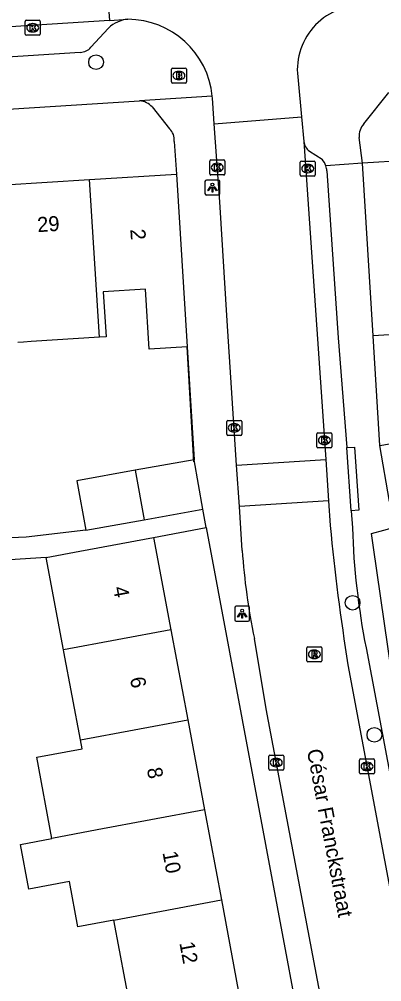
# Model space of a CAD drawing. Extents: x 159053 to 160041, y 380450 to 381422.
# Drawn here: x 159871.5 to 159895.7, y 380943.6 to 381007.6 of the extents above; entities that cross this region are included whole.
import ezdxf

# ---------------------------------------------------------------- set-up
doc = ezdxf.new("R2010")
doc.units = 0
for name, color, linetype in [('IMGEO_Boom', 7, 'Continuous'), ('IMGEO_Brandkraan', 7, 'Continuous'), ('IMGEO_Kolk', 7, 'Continuous'), ('IMGEO_Lichtpunt', 7, 'Continuous'), ('IMGEO_Muur', 7, 'Continuous'), ('IMGEO_Openbare_ruimte_label', 7, 'Continuous'), ('IMGEO_Pand', 7, 'Continuous'), ('IMGEO_Pand_nummerreeks', 7, 'Continuous'), ('IMGEO_Rijbaan_lokaal_open', 7, 'Continuous'), ('IMGEO_Rioolput', 7, 'Continuous'), ('IMGEO_Voetpad_open', 7, 'Continuous')]:
    doc.layers.add(name, color=color, linetype=linetype)

msp = doc.modelspace()

# ---------------------------------------------------------------- linework, layer by layer
at = {"layer": 'IMGEO_Boom'}
for centre in [(159876.626, 381004.767), (159893.724, 380968.791), (159895.174, 380960.006)]:
    msp.add_circle(centre, 0.489, dxfattribs=at)
at = {"layer": 'IMGEO_Brandkraan'}
for p, q in [((159881.646, 381003.451), (159881.646, 381004.303)), ((159881.721, 381004.377), (159882.573, 381004.377)), ((159882.134, 381004.157), (159882.159, 381004.157)), ((159882.647, 381004.303), (159882.647, 381003.451)), ((159882.573, 381003.377), (159881.721, 381003.377)), ((159882.157, 381003.597), (159882.132, 381003.597))]:
    msp.add_line(p, q, dxfattribs=at)
for points in [[(159881.646, 381003.451), (159881.646, 381004.303)], [(159881.721, 381004.377), (159882.573, 381004.377)], [(159881.994, 381004.077), (159881.994, 381003.677), (159882.207, 381003.677)], [(159882.225, 381004.077), (159881.994, 381004.077)], [(159882.173, 381003.996), (159882.119, 381003.996), (159882.119, 381003.92)], [(159882.647, 381004.303), (159882.647, 381003.451)], [(159882.573, 381003.377), (159881.721, 381003.377)], [(159882.119, 381003.92), (159882.172, 381003.92)], [(159882.181, 381003.844), (159882.119, 381003.844), (159882.119, 381003.763)], [(159882.119, 381003.763), (159882.181, 381003.763)]]:
    msp.add_lwpolyline(points, dxfattribs=at)
for centre, radius, start, end in [((159881.723, 381004.301), 0.0765, 91.55205, 178.44795), ((159881.723, 381004.301), 0.0765, 91.55205, 178.44795), ((159882.174, 381003.958), 0.0379, 267.82845, 90.93552), ((159882.229, 381003.932), 0.145, 59.4692, 91.53667), ((159882.254, 381003.979), 0.0922, 285.51372, 58.15012), ((159882.571, 381004.301), 0.0765, 1.55205, 88.44795), ((159882.571, 381004.301), 0.0765, 1.55205, 88.44795), ((159881.723, 381003.453), 0.0765, 181.55205, 268.44795), ((159881.723, 381003.453), 0.0765, 181.55205, 268.44795), ((159882.182, 381003.803), 0.0404, 269.87594, 90.50774), ((159882.213, 381003.928), 0.251, 268.66757, 293.53466), ((159882.259, 381003.787), 0.105, 301.31148, 78.98903), ((159882.571, 381003.453), 0.0765, 271.55205, 358.44795), ((159882.571, 381003.453), 0.0765, 271.55205, 358.44795)]:
    msp.add_arc(centre, radius, start, end, dxfattribs=at)
for centre, major_axis, ratio, start_param, end_param in [((159882.133, 381003.877), (-0.387, 0.002), 0.722429, 4.712389, 7.853982), ((159882.158, 381003.877), (-0.39, 0.002), 0.717154, 1.570796, 4.712389)]:
    msp.add_ellipse(centre, major_axis=major_axis, ratio=ratio, start_param=start_param, end_param=end_param, dxfattribs=at)
at = {"layer": 'IMGEO_Kolk'}
for p, q in [((159871.908, 381006.63), (159871.908, 381007.482)), ((159871.983, 381007.556), (159872.835, 381007.556)), ((159872.396, 381007.336), (159872.421, 381007.336)), ((159872.909, 381007.482), (159872.909, 381006.63)), ((159872.835, 381006.556), (159871.983, 381006.556)), ((159872.419, 381006.776), (159872.394, 381006.776)), ((159884.282, 380998.259), (159885.134, 380998.259)), ((159884.207, 380997.333), (159884.207, 380998.185)), ((159884.695, 380998.039), (159884.72, 380998.039)), ((159885.208, 380998.185), (159885.208, 380997.333)), ((159890.234, 380997.259), (159890.234, 380998.111)), ((159890.309, 380998.185), (159891.161, 380998.185)), ((159890.722, 380997.965), (159890.747, 380997.965)), ((159891.235, 380998.111), (159891.235, 380997.259)), ((159885.134, 380997.259), (159884.282, 380997.259)), ((159884.718, 380997.479), (159884.693, 380997.479)), ((159891.161, 380997.185), (159890.309, 380997.185)), ((159890.745, 380997.405), (159890.72, 380997.405)), ((159885.409, 380980.932), (159886.261, 380980.932)), ((159885.334, 380980.006), (159885.334, 380980.858)), ((159885.822, 380980.712), (159885.847, 380980.712)), ((159886.335, 380980.858), (159886.335, 380980.006)), ((159886.261, 380979.932), (159885.409, 380979.932)), ((159885.845, 380980.152), (159885.82, 380980.152)), ((159891.344, 380979.177), (159891.344, 380980.029)), ((159891.419, 380980.103), (159892.271, 380980.103)), ((159891.832, 380979.883), (159891.857, 380979.883)), ((159892.345, 380980.029), (159892.345, 380979.177)), ((159892.271, 380979.103), (159891.419, 380979.103)), ((159891.855, 380979.323), (159891.83, 380979.323)), ((159888.134, 380957.733), (159888.134, 380958.585)), ((159888.209, 380958.659), (159889.061, 380958.659)), ((159889.135, 380958.585), (159889.135, 380957.733)), ((159888.645, 380957.879), (159888.62, 380957.879)), ((159888.622, 380958.439), (159888.647, 380958.439)), ((159894.185, 380957.477), (159894.185, 380958.329)), ((159894.26, 380958.403), (159895.112, 380958.403)), ((159894.673, 380958.183), (159894.698, 380958.183)), ((159895.186, 380958.329), (159895.186, 380957.477)), ((159889.061, 380957.659), (159888.209, 380957.659)), ((159895.112, 380957.403), (159894.26, 380957.403)), ((159894.696, 380957.623), (159894.671, 380957.623))]:
    msp.add_line(p, q, dxfattribs=at)
for points in [[(159871.908, 381006.63), (159871.908, 381007.482)], [(159871.983, 381007.556), (159872.835, 381007.556)], [(159872.229, 381007.256), (159872.352, 381007.256), (159872.352, 381007.105), (159872.482, 381007.256), (159872.646, 381007.256), (159872.5, 381007.105), (159872.653, 381006.856), (159872.501, 381006.856), (159872.416, 381007.02), (159872.352, 381006.953), (159872.352, 381006.856), (159872.229, 381006.856), (159872.229, 381007.256)], [(159872.909, 381007.482), (159872.909, 381006.63)], [(159872.835, 381006.556), (159871.983, 381006.556)], [(159884.282, 380998.259), (159885.134, 380998.259)], [(159884.207, 380997.333), (159884.207, 380998.185)], [(159884.528, 380997.959), (159884.651, 380997.959), (159884.651, 380997.808), (159884.781, 380997.959), (159884.945, 380997.959), (159884.799, 380997.808), (159884.952, 380997.559), (159884.8, 380997.559), (159884.715, 380997.723), (159884.651, 380997.656), (159884.651, 380997.559), (159884.528, 380997.559), (159884.528, 380997.959)], [(159885.208, 380998.185), (159885.208, 380997.333)], [(159890.234, 380997.259), (159890.234, 380998.111)], [(159890.309, 380998.185), (159891.161, 380998.185)], [(159890.555, 380997.885), (159890.678, 380997.885), (159890.678, 380997.734), (159890.808, 380997.885), (159890.972, 380997.885), (159890.826, 380997.734), (159890.979, 380997.485), (159890.827, 380997.485), (159890.742, 380997.649), (159890.678, 380997.582), (159890.678, 380997.485), (159890.555, 380997.485), (159890.555, 380997.885)], [(159891.235, 380998.111), (159891.235, 380997.259)], [(159885.134, 380997.259), (159884.282, 380997.259)], [(159891.161, 380997.185), (159890.309, 380997.185)], [(159885.409, 380980.932), (159886.261, 380980.932)], [(159885.334, 380980.006), (159885.334, 380980.858)], [(159885.655, 380980.632), (159885.778, 380980.632), (159885.778, 380980.481), (159885.908, 380980.632), (159886.072, 380980.632), (159885.926, 380980.481), (159886.079, 380980.232), (159885.927, 380980.232), (159885.842, 380980.396), (159885.778, 380980.329), (159885.778, 380980.232), (159885.655, 380980.232), (159885.655, 380980.632)], [(159886.335, 380980.858), (159886.335, 380980.006)], [(159886.261, 380979.932), (159885.409, 380979.932)], [(159891.344, 380979.177), (159891.344, 380980.029)], [(159891.419, 380980.103), (159892.271, 380980.103)], [(159891.665, 380979.803), (159891.788, 380979.803), (159891.788, 380979.652), (159891.918, 380979.803), (159892.082, 380979.803), (159891.936, 380979.652), (159892.089, 380979.403), (159891.937, 380979.403), (159891.852, 380979.567), (159891.788, 380979.5), (159891.788, 380979.403), (159891.665, 380979.403), (159891.665, 380979.803)], [(159892.345, 380980.029), (159892.345, 380979.177)], [(159892.271, 380979.103), (159891.419, 380979.103)], [(159888.134, 380957.733), (159888.134, 380958.585)], [(159888.209, 380958.659), (159889.061, 380958.659)], [(159889.135, 380958.585), (159889.135, 380957.733)], [(159888.455, 380958.359), (159888.578, 380958.359), (159888.578, 380958.208), (159888.708, 380958.359), (159888.872, 380958.359), (159888.726, 380958.208), (159888.879, 380957.959), (159888.727, 380957.959), (159888.642, 380958.123), (159888.578, 380958.056), (159888.578, 380957.959), (159888.455, 380957.959), (159888.455, 380958.359)], [(159894.185, 380957.477), (159894.185, 380958.329)], [(159894.26, 380958.403), (159895.112, 380958.403)], [(159894.506, 380958.103), (159894.629, 380958.103), (159894.629, 380957.952), (159894.759, 380958.103), (159894.923, 380958.103), (159894.777, 380957.952), (159894.93, 380957.703), (159894.778, 380957.703), (159894.693, 380957.867), (159894.629, 380957.8), (159894.629, 380957.703), (159894.506, 380957.703), (159894.506, 380958.103)], [(159895.186, 380958.329), (159895.186, 380957.477)], [(159889.061, 380957.659), (159888.209, 380957.659)], [(159895.112, 380957.403), (159894.26, 380957.403)]]:
    msp.add_lwpolyline(points, dxfattribs=at)
for centre, start, end in [((159871.985, 381007.48), 91.55205, 178.44795), ((159871.985, 381007.48), 91.55205, 178.44795), ((159872.833, 381007.48), 1.55205, 88.44795), ((159872.833, 381007.48), 1.55205, 88.44795), ((159871.985, 381006.632), 181.55205, 268.44795), ((159871.985, 381006.632), 181.55205, 268.44795), ((159872.833, 381006.632), 271.55205, 358.44795), ((159872.833, 381006.632), 271.55205, 358.44795), ((159884.284, 380998.183), 91.55205, 178.44795), ((159884.284, 380998.183), 91.55205, 178.44795), ((159885.132, 380998.183), 1.55205, 88.44795), ((159885.132, 380998.183), 1.55205, 88.44795), ((159890.311, 380998.109), 91.55205, 178.44795), ((159890.311, 380998.109), 91.55205, 178.44795), ((159891.159, 380998.109), 1.55205, 88.44795), ((159891.159, 380998.109), 1.55205, 88.44795), ((159884.284, 380997.335), 181.55205, 268.44795), ((159884.284, 380997.335), 181.55205, 268.44795), ((159885.132, 380997.335), 271.55205, 358.44795), ((159885.132, 380997.335), 271.55205, 358.44795), ((159890.311, 380997.261), 181.55205, 268.44795), ((159890.311, 380997.261), 181.55205, 268.44795), ((159891.159, 380997.261), 271.55205, 358.44795), ((159891.159, 380997.261), 271.55205, 358.44795), ((159885.411, 380980.856), 91.55205, 178.44795), ((159885.411, 380980.856), 91.55205, 178.44795), ((159886.259, 380980.856), 1.55205, 88.44795), ((159886.259, 380980.856), 1.55205, 88.44795), ((159885.411, 380980.008), 181.55205, 268.44795), ((159885.411, 380980.008), 181.55205, 268.44795), ((159886.259, 380980.008), 271.55205, 358.44795), ((159886.259, 380980.008), 271.55205, 358.44795), ((159891.421, 380980.027), 91.55205, 178.44795), ((159891.421, 380980.027), 91.55205, 178.44795), ((159892.269, 380980.027), 1.55205, 88.44795), ((159892.269, 380980.027), 1.55205, 88.44795), ((159891.421, 380979.179), 181.55205, 268.44795), ((159891.421, 380979.179), 181.55205, 268.44795), ((159892.269, 380979.179), 271.55205, 358.44795), ((159892.269, 380979.179), 271.55205, 358.44795), ((159888.211, 380958.583), 91.55205, 178.44795), ((159888.211, 380958.583), 91.55205, 178.44795), ((159889.059, 380958.583), 1.55205, 88.44795), ((159889.059, 380958.583), 1.55205, 88.44795), ((159894.262, 380958.327), 91.55205, 178.44795), ((159894.262, 380958.327), 91.55205, 178.44795), ((159895.11, 380958.327), 1.55205, 88.44795), ((159895.11, 380958.327), 1.55205, 88.44795), ((159888.211, 380957.735), 181.55205, 268.44795), ((159888.211, 380957.735), 181.55205, 268.44795), ((159889.059, 380957.735), 271.55205, 358.44795), ((159889.059, 380957.735), 271.55205, 358.44795), ((159894.262, 380957.479), 181.55205, 268.44795), ((159894.262, 380957.479), 181.55205, 268.44795), ((159895.11, 380957.479), 271.55205, 358.44795), ((159895.11, 380957.479), 271.55205, 358.44795)]:
    msp.add_arc(centre, 0.0765, start, end, dxfattribs=at)
for centre, major_axis, ratio, start_param, end_param in [((159872.395, 381007.056), (-0.387, 0.002), 0.722429, 4.712389, 7.853982), ((159872.42, 381007.056), (-0.39, 0.002), 0.717154, 1.570796, 4.712389), ((159884.694, 380997.759), (-0.387, 0.002), 0.722429, 4.712389, 7.853982), ((159884.719, 380997.759), (-0.39, 0.002), 0.717154, 1.570796, 4.712389), ((159890.721, 380997.685), (-0.387, 0.002), 0.722429, 4.712389, 7.853982), ((159890.746, 380997.685), (-0.39, 0.002), 0.717154, 1.570796, 4.712389), ((159885.821, 380980.432), (-0.387, 0.002), 0.722429, 4.712389, 7.853982), ((159885.846, 380980.432), (-0.39, 0.002), 0.717154, 1.570796, 4.712389), ((159891.831, 380979.603), (-0.387, 0.002), 0.722429, 4.712389, 7.853982), ((159891.856, 380979.603), (-0.39, 0.002), 0.717154, 1.570796, 4.712389), ((159888.621, 380958.159), (-0.387, 0.002), 0.722429, 4.712389, 7.853982), ((159888.646, 380958.159), (-0.39, 0.002), 0.717154, 1.570796, 4.712389), ((159894.672, 380957.903), (-0.387, 0.002), 0.722429, 4.712389, 7.853982), ((159894.697, 380957.903), (-0.39, 0.002), 0.717154, 1.570796, 4.712389)]:
    msp.add_ellipse(centre, major_axis=major_axis, ratio=ratio, start_param=start_param, end_param=end_param, dxfattribs=at)
at = {"layer": 'IMGEO_Lichtpunt'}
for p, q in [((159883.884, 380996.829), (159883.884, 380996.022)), ((159883.884, 380996.829), (159883.884, 380996.022)), ((159884.786, 380996.924), (159883.978, 380996.924)), ((159884.786, 380996.924), (159883.978, 380996.924)), ((159884.88, 380996.022), (159884.88, 380996.829)), ((159884.88, 380996.022), (159884.88, 380996.829)), ((159883.978, 380995.928), (159884.786, 380995.928)), ((159883.978, 380995.928), (159884.786, 380995.928)), ((159885.867, 380968.466), (159885.867, 380967.659)), ((159885.867, 380968.466), (159885.867, 380967.659)), ((159886.769, 380968.561), (159885.961, 380968.561)), ((159886.769, 380968.561), (159885.961, 380968.561)), ((159886.863, 380967.659), (159886.863, 380968.466)), ((159886.863, 380967.659), (159886.863, 380968.466)), ((159885.961, 380967.565), (159886.769, 380967.565)), ((159885.961, 380967.565), (159886.769, 380967.565))]:
    msp.add_line(p, q, dxfattribs=at)
for points in [[(159884.258, 380996.493), (159884.297, 380996.465), (159884.109, 380996.203), (159884.071, 380996.23), (159884.258, 380996.493)], [(159884.36, 380996.445), (159884.407, 380996.445), (159884.407, 380996.123), (159884.36, 380996.123), (159884.36, 380996.445)], [(159884.47, 380996.465), (159884.508, 380996.492), (159884.695, 380996.23), (159884.656, 380996.202), (159884.47, 380996.465)], [(159886.241, 380968.13), (159886.28, 380968.102), (159886.092, 380967.84), (159886.054, 380967.867), (159886.241, 380968.13)], [(159886.453, 380968.102), (159886.491, 380968.129), (159886.678, 380967.867), (159886.639, 380967.839), (159886.453, 380968.102)], [(159886.343, 380968.082), (159886.39, 380968.082), (159886.39, 380967.76), (159886.343, 380967.76), (159886.343, 380968.082)]]:
    msp.add_lwpolyline(points, dxfattribs=at)
for centre in [(159884.383, 380996.627), (159886.366, 380968.264)]:
    msp.add_circle(centre, 0.0994, dxfattribs=at)
for centre, start, end in [((159883.978, 380996.829), 90, 180), ((159883.978, 380996.829), 90, 180), ((159884.786, 380996.829), 0, 90), ((159884.786, 380996.829), 0, 90), ((159883.978, 380996.022), 180, 270), ((159883.978, 380996.022), 180, 270), ((159884.786, 380996.022), 270, 0), ((159884.786, 380996.022), 270, 360), ((159885.961, 380968.466), 90, 180), ((159885.961, 380968.466), 90, 180), ((159886.769, 380968.466), 0, 90), ((159886.769, 380968.466), 0, 90), ((159885.961, 380967.659), 180, 270), ((159885.961, 380967.659), 180, 270), ((159886.769, 380967.659), 270, 0), ((159886.769, 380967.659), 270, 360)]:
    msp.add_arc(centre, 0.0946, start, end, dxfattribs=at)
at = {"layer": 'IMGEO_Muur'}
for points in [[(159895.537, 380979.263), (159895.09, 380986.56)], [(159883.145, 380978.174), (159882.693, 380985.831)]]:
    msp.add_lwpolyline(points, dxfattribs=at)
at = {"layer": 'IMGEO_Pand'}
for points in [[(159900.212, 380998.406), (159894.379, 380998.038)], [(159895.09, 380986.56), (159894.379, 380998.038)], [(159870.549, 380996.6), (159876.182, 380996.957)], [(159876.182, 380996.957), (159881.998, 380997.324)], [(159876.847, 380986.463), (159876.182, 380996.957)], [(159881.998, 380997.324), (159882.693, 380985.831)], [(159900.704, 380991.068), (159900.213, 380991.038), (159900.47, 380986.894), (159895.09, 380986.56)], [(159882.693, 380985.831), (159880.169, 380985.671), (159879.916, 380989.672), (159877.112, 380989.494), (159877.303, 380986.492), (159876.847, 380986.463)], [(159876.847, 380986.463), (159872.314, 380986.175), (159871.784, 380986.141), (159871.422, 380986.118)], [(159895.537, 380979.263), (159901.194, 380980.235), (159901.721, 380976.335)], [(159896.179, 380975.527), (159895.537, 380979.263)], [(159883.159, 380978.314), (159879.245, 380977.613)], [(159883.748, 380975.023), (159883.159, 380978.314)], [(159879.245, 380977.613), (159875.351, 380976.915), (159875.941, 380973.624)], [(159879.245, 380977.613), (159879.835, 380974.321)], [(159879.835, 380974.321), (159883.748, 380975.023)], [(159875.941, 380973.624), (159879.835, 380974.321)], [(159873.309, 380971.804), (159875.553, 380972.224), (159880.467, 380973.143)], [(159880.467, 380973.143), (159881.616, 380967.002)], [(159874.457, 380965.661), (159873.309, 380971.804)], [(159881.616, 380967.002), (159874.457, 380965.661)], [(159881.616, 380967.002), (159882.737, 380961.009)], [(159875.581, 380959.667), (159874.484, 380965.531), (159874.457, 380965.661)], [(159875.581, 380959.667), (159882.737, 380961.009)], [(159882.737, 380961.009), (159883.858, 380955.013)], [(159873.684, 380953.107), (159872.674, 380958.511), (159875.692, 380959.075), (159875.581, 380959.667)], [(159883.858, 380955.013), (159876.702, 380953.672), (159873.684, 380953.107)], [(159883.858, 380955.013), (159884.979, 380949.019)], [(159877.823, 380947.678), (159875.416, 380947.227), (159874.85, 380950.251), (159872.15, 380949.745), (159871.594, 380952.715), (159873.684, 380953.107)], [(159877.823, 380947.678), (159884.979, 380949.019)], [(159884.979, 380949.019), (159886.101, 380943.023)], [(159878.944, 380941.681), (159877.823, 380947.678)]]:
    msp.add_lwpolyline(points, dxfattribs=at)
at = {"layer": 'IMGEO_Rijbaan_lokaal_open'}
for points in [[(159877.054, 381013.51), (159877.532, 381007.54)], [(159877.532, 381007.54), (159828.208, 381004.391)], [(159877.532, 381007.54), (159878.741, 381007.623)], [(159890.098, 381003.554), (159890.315, 381001.12)], [(159884.499, 381000.667), (159884.404, 381002.033)], [(159884.499, 381000.667), (159890.315, 381001.12)], [(159890.315, 381001.12), (159890.474, 380999.493)], [(159885.998, 380977.948), (159885.374, 380987.549), (159884.872, 380995.483), (159884.499, 381000.667)], [(159890.474, 380999.493), (159891.931, 380978.334)], [(159885.998, 380977.948), (159891.931, 380978.334)], [(159886.177, 380975.194), (159885.998, 380977.948)], [(159891.931, 380978.334), (159892.12, 380975.581)], [(159892.12, 380975.581), (159886.177, 380975.194)], [(159886.366, 380972.278), (159886.177, 380975.194)], [(159892.12, 380975.581), (159892.233, 380973.926)], [(159896.76, 380915.304), (159887.958, 380961.731), (159887.177, 380966.41)], [(159893.418, 380964.653), (159898.292, 380938.671), (159902.573, 380916.365)]]:
    msp.add_lwpolyline(points, dxfattribs=at)
for centre, radius, start, end in [((159894.334, 381004.251), 4.293, 88.62025, 189.34054), ((159878.717, 381001.936), 5.687, 5.64142, 89.76264), ((159878.52, 381001.921), 5.885, 1.09132, 5.59798), ((160035.188, 380987.482), 143.596, 185.41701, 189.14774), ((159929.965, 380975.314), 43.705, 183.9829, 191.75478)]:
    msp.add_arc(centre, radius, start, end, dxfattribs=at)
at = {"layer": 'IMGEO_Rioolput'}
for p, q in [((159890.676, 380964.937), (159890.676, 380965.789)), ((159890.751, 380965.863), (159891.603, 380965.863)), ((159891.164, 380965.643), (159891.189, 380965.643)), ((159891.677, 380965.789), (159891.677, 380964.937)), ((159891.187, 380965.083), (159891.162, 380965.083)), ((159891.603, 380964.863), (159890.751, 380964.863))]:
    msp.add_line(p, q, dxfattribs=at)
for points in [[(159890.676, 380964.937), (159890.676, 380965.789)], [(159890.751, 380965.863), (159891.603, 380965.863)], [(159891.265, 380965.561), (159891.013, 380965.563), (159891.013, 380965.163)], [(159891.677, 380965.789), (159891.677, 380964.937)], [(159891.013, 380965.163), (159891.137, 380965.163), (159891.137, 380965.325), (159891.148, 380965.325)], [(159891.191, 380965.482), (159891.137, 380965.482), (159891.137, 380965.401)], [(159891.137, 380965.401), (159891.189, 380965.401)], [(159891.195, 380965.296), (159891.266, 380965.163), (159891.406, 380965.163), (159891.341, 380965.289)], [(159891.603, 380964.863), (159890.751, 380964.863)]]:
    msp.add_lwpolyline(points, dxfattribs=at)
for centre, radius, start, end in [((159890.753, 380965.787), 0.0765, 91.55205, 178.44795), ((159890.753, 380965.787), 0.0765, 91.55205, 178.44795), ((159891.264, 380965.451), 0.109, 350.36119, 89.41601), ((159891.601, 380965.787), 0.0765, 1.55205, 88.44795), ((159891.601, 380965.787), 0.0765, 1.55205, 88.44795), ((159890.753, 380964.939), 0.0765, 181.55205, 268.44795), ((159890.753, 380964.939), 0.0765, 181.55205, 268.44795), ((159891.147, 380965.272), 0.0533, 26.02933, 88.69889), ((159891.173, 380965.59), 0.19, 274.7715, 282.96867), ((159891.197, 380965.386), 0.0964, 77.00612, 93.18647), ((159891.211, 380965.443), 0.0378, 276.66336, 79.67722), ((159891.262, 380965.451), 0.112, 277.58423, 350.98172), ((159891.246, 380965.236), 0.108, 29.51342, 73.79051), ((159891.601, 380964.939), 0.0765, 271.55205, 358.44795), ((159891.601, 380964.939), 0.0765, 271.55205, 358.44795)]:
    msp.add_arc(centre, radius, start, end, dxfattribs=at)
for centre, major_axis, ratio, start_param, end_param in [((159891.163, 380965.363), (-0.387, 0.002), 0.722429, 4.712389, 7.853982), ((159891.188, 380965.363), (-0.39, 0.002), 0.717154, 1.570796, 4.712389)]:
    msp.add_ellipse(centre, major_axis=major_axis, ratio=ratio, start_param=start_param, end_param=end_param, dxfattribs=at)
at = {"layer": 'IMGEO_Voetpad_open'}
for points in [[(159877.458, 381007.039), (159876.288, 381005.762)], [(159875.572, 381005.419), (159853.039, 381003.979), (159830.438, 381002.526)], [(159894.471, 381000.655), (159896.145, 381002.748)], [(159831.207, 380999.131), (159879.533, 381002.193)], [(159884.377, 381002.495), (159879.533, 381002.193)], [(159880.371, 381001.788), (159881.523, 381000.338)], [(159894.379, 380998.038), (159894.165, 380999.763)], [(159881.838, 380999.49), (159881.998, 380997.324)], [(159890.85, 380998.846), (159891.686, 380998.305)], [(159894.379, 380998.038), (159891.952, 380997.861)], [(159892.005, 380997.538), (159892.762, 380986.423), (159893.35, 380979.119)], [(159895.537, 380979.263), (159895.09, 380986.56)], [(159882.693, 380985.831), (159883.159, 380978.314)], [(159893.35, 380979.119), (159893.849, 380979.152), (159894.135, 380974.951), (159893.636, 380974.918)], [(159893.636, 380974.918), (159893.35, 380979.119)], [(159883.964, 380973.797), (159883.748, 380975.023)], [(159893.636, 380974.918), (159893.714, 380973.778)], [(159875.941, 380973.624), (159871.963, 380973.148), (159870.955, 380973.106)], [(159880.467, 380973.143), (159883.964, 380973.797)], [(159883.964, 380973.797), (159895.062, 380914.655), (159895.25, 380913.652), (159894.212, 380913.429), (159891.735, 380912.898)], [(159905.957, 380913.158), (159896.323, 380964.203), (159895.118, 380972.466), (159894.983, 380973.394), (159895.81, 380973.629), (159896.522, 380973.831)], [(159873.309, 380971.804), (159860.505, 380970.994)], [(159894.619, 380965.794), (159904.289, 380914.542), (159904.885, 380911.303)]]:
    msp.add_lwpolyline(points, dxfattribs=at)
for centre, radius, start, end in [((159878.951, 381005.46), 2.173, 95.54851, 133.39995), ((159875.541, 381006.402), 0.984, 271.79921, 319.39431), ((159879.445, 381000.941), 1.255, 42.44525, 85.96639), ((159880.827, 380999.597), 1.017, 353.96159, 46.79468), ((159895.341, 380999.858), 1.179, 137.50112, 184.62989), ((159891.354, 380999.572), 0.884, 185.11781, 235.20768), ((159890.844, 380997.499), 1.166, 18.09893, 43.75264), ((159890.844, 380997.513), 1.161, 1.21603, 17.42084), ((159943.133, 380975.336), 49.444, 181.80628, 191.12766)]:
    msp.add_arc(centre, radius, start, end, dxfattribs=at)

# ---------------------------------------------------------------- texts
at = {"layer": 'IMGEO_Openbare_ruimte_label'}
msp.add_text('César Franckstraat', height=1, rotation=280.71464, dxfattribs=at).set_placement((159890.672, 380958.973))
at = {"layer": 'IMGEO_Pand_nummerreeks'}
for s, rotation, p in [('29', 3.63006, (159872.739, 380993.452)), ('2', 273.6294, (159878.91, 380993.646)), ('4', 280.59378, (159877.756, 380969.799)), ('6', 280.59399, (159878.883, 380963.774)), ('8', 280.59378, (159880.009, 380957.746)), ('10', 280.59378, (159881.052, 380952.173)), ('12', 280.59399, (159882.178, 380946.156))]:
    msp.add_text(s, height=1, rotation=rotation, dxfattribs=at).set_placement(p)

doc.saveas('drawing.dxf')
